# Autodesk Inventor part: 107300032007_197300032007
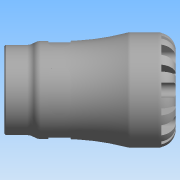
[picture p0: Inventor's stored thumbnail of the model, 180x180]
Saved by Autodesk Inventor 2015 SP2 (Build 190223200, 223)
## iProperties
Created: 2016-12
Part Number: 107300032007_197300032007
Material: Generic
Description: PLASSON FEMALE INTEGRAL BRASS THREAD 32X3/4" SERIES 1
Document SubType Name: Modeling
Designer: KIM
Density: 1 g/cm^3
Appearance: Default
Author: KIM
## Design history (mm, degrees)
derived "1073.ipt"
feature "Solid1::1073.ipt"
tag "TaggingFeature1"
body "Solid1"
other parameters: "d0" = 86, "d1" = 23.52, "d2" = 32, "d4" = 58, "d6" = 56, "d8" = 49.3, "d13" = 7.2, "d14" = 7.2, "d15" = 0, "d17" = 360 deg, "d19" = 8 deg, "d20" = 0.64, "d21" = 0.64, "d22" = 8 deg, "d24" = 0, "d26" = 360 deg, "d32" = 5.8, "d33" = 5.8, "d39" = 0.72351, "d42" = 24.117, "d43" = 45.24, "d46" = 2.66667, "d47" = 16, "d48" = 22.91115, "d50" = 4.62, "d51" = 0.58, "d54" = 11.2, "d55" = 7.04, "d57" = 14.112, "d58" = 0, "d68" = 360 deg, "d72" = 0.64, "d74" = 0, "d76" = 9.52, "d_" = 32, "E_" = 58, "H_" = 86, "l_" = 56, "G_" = 24.117, "l_2" = 16, "d9" = 9, "d11" = 58, "d49" = 14
